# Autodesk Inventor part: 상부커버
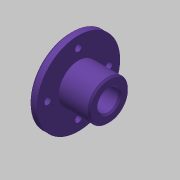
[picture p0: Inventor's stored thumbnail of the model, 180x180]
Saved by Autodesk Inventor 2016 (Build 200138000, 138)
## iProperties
Created: 2015-09
Part Number: 상부커버
Material: 알루미늄 6061
Document SubType Name: Modeling
Designer: mduedu
Density: 1 g/cm^3
Appearance: 보라색
Author: mduedu
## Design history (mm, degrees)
sketch "스케치1"
  geometry: L1 (-12.5, 0)-(12.5, 0); L2 (-12.5, 0)-(-12.5, 27); L3 (-12.5, 27)-(-7.5, 27); L4 (-7.5, 27)-(-7.5, 13); L5 (-7.5, 13)-(12.5, 13); L6 (12.5, 13)-(12.5, 0); 2 further points
  constraints: 12 end point, 2 parallel, 2 perpendicular, 1 coincident, 1 horizontal, 1 midpoint, 1 vertical
  dimensions: "d0" = 25 distance of L1.start L1.end; "d2" = 5 distance of L2.end L3.end; "d3" = 26 diameter of L5 L1; "d4" = 54 diameter of L3 L1
revolve "회전1" sketch "스케치1" stored, may be unused: angle "d5" = 90 deg
hole "구멍1" diameter "d8" = 14; stored, may be unused: countersink angle "d12" = 90 deg, drill point angle "d14" = 118 deg; dims "d6" = 10, "d7" = 10, "d9" = 6, "d10" = 4, "d11" = 2, "d13" = 8
chamfer "모따기1" distance "d15" = 1; stored, may be unused: second distance "d16" = 2, angle "d17" = 45 deg
chamfer "모따기2" distance "d18" = 1; stored, may be unused: second distance "d19" = 2, angle "d20" = 45 deg
sketch "스케치2" dims "d21" = 40
  geometry: 6 further points
  constraints: 2 vertical alignment, 1 coincident, 7 other
  dimensions: "d25" = 360 deg dimension on point (0, 0) point (0, 20) (derived)
sketch "스케치3"
  geometry: 4 further points
hole "구멍2" sketch "스케치3" at (0, 20), (-20, 0), (20, 0), (0, -20) diameter "d27" = 4.5; stored, may be unused: countersink angle "d31" = 90 deg, drill point angle "d33" = 0 deg; dims "d28" = 6, "d29" = 4, "d30" = 2, "d32" = 8
chamfer "모따기3" distance "d34" = 1; stored, may be unused: second distance "d35" = 2, angle "d36" = 45 deg
node "솔리드1"
